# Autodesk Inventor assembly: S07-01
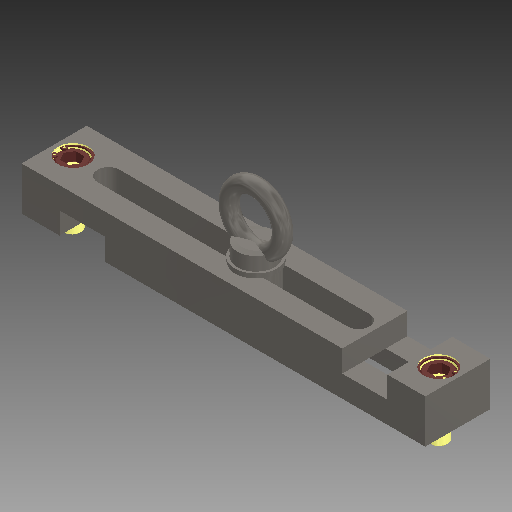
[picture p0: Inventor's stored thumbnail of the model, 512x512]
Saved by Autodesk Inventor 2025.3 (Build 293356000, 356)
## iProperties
Created: 2025-03
Part Number: S07-01
Document SubType Name: Assembly
Designer: Patrik
Description: Transportní systém
Stock Number: Z70_3
User Status: 1.2312
Vendor: Hasco
Sending System: HASCO Hasenclever GmbH & Co. KG
Major Version: 4.0
Minor Version: 0.0
Format Version: 0.0
Product Id: HASCO Hasenclever GmbH & Co. KG
Bestellnummer: Z70/3
Benennung: Lifting device
Hersteller: HASCO
Material: 0
Dichte: 0
Author: Patrik
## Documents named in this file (10)
- C:\Users\Patrik\Documents\Skola\Bakalarska prace\Prakticka cast\Hasco - sestava - transport\Z70_3.iam
- C:\Users\Patrik\Documents\Skola\Bakalarska prace\Prakticka cast\Hasco - sestava - transport\Z70_3.ipt
- C:\Users\Patrik\Documents\Skola\Bakalarska prace\Prakticka cast\Hasco - sestava - transport\Z70_3_1.ipt
- C:\Users\Patrik\Documents\Skola\Bakalarska prace\Prakticka cast\Hasco - sestava - transport\Z70_3_2.ipt
- C:\Users\Patrik\Documents\Skola\Bakalarska prace\Prakticka cast\Hasco - sestava - transport\Z70_3_3.ipt
- C:\Users\Patrik\Documents\Skola\Bakalarska prace\Prakticka cast\Hasco - sestava - transport\Z70_3_4.ipt
- C:\Users\Patrik\Documents\Skola\Bakalarska prace\Prakticka cast\Hasco - sestava - transport\Z70_3_5.ipt
- C:\Users\Patrik\Documents\Skola\Bakalarska prace\Prakticka cast\Hasco - sestava - transport\Z70_3_6.ipt
- C:\Users\Patrik\Documents\Skola\Bakalarska prace\Prakticka cast\Hasco - sestava - transport\Z70_3_7.ipt
- C:\Users\Patrik\Documents\Skola\Bakalarska prace\Prakticka cast\Hasco - sestava - transport\Z70_3_8.ipt
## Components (9 placed, 9 different names)
1. Z70_3_1:1 — Proti sobě:1, Stejný směr:1, Vložit:4, Proti sobě:5, Proti sobě:6, Proti sobě:7
2. Z70_3_2:1 — Proti sobě:1, Stejný směr:1, Vložit:1, Proti sobě:2, Proti sobě:7
3. Z70_3_3:1 — Proti sobě:3, Proti sobě:5, Proti sobě:6
4. Z70_3_4:1 — Proti sobě:2, Proti sobě:3, Vložit:3
5. Z70_3_5:1 — Vložit:5
6. Z70_3_6:1 — Vložit:2
7. Z70_3_7:1 — Vložit:3
8. Z70_3_8:1 — Vložit:4, Vložit:5
9. Z70_3_9:1 — Vložit:1, Vložit:2
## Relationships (12: Mate 6, Insert 5, Flush 1)
- Proti sobě:1 [Mate]: Z70_3_1:1 ↔ Z70_3_2:1
- Stejný směr:1 [Flush]: Z70_3_1:1 ↔ Z70_3_2:1
- Vložit:1 [Insert]: Z70_3_2:1 ↔ Z70_3_9:1
- Vložit:2 [Insert]: Z70_3_6:1 ↔ Z70_3_9:1
- Proti sobě:2 [Mate]: Z70_3_2:1 ↔ Z70_3_4:1
- Proti sobě:3 [Mate]: Z70_3_3:1 ↔ Z70_3_4:1
- Vložit:3 [Insert]: Z70_3_4:1 ↔ Z70_3_7:1
- Vložit:4 [Insert]: Z70_3_1:1 ↔ Z70_3_8:1
- Vložit:5 [Insert]: Z70_3_5:1 ↔ Z70_3_8:1
- Proti sobě:5 [Mate]: Z70_3_1:1 ↔ Z70_3_3:1
- Proti sobě:6 [Mate]: Z70_3_1:1 ↔ Z70_3_3:1
- Proti sobě:7 [Mate]: Z70_3_1:1 ↔ Z70_3_2:1
